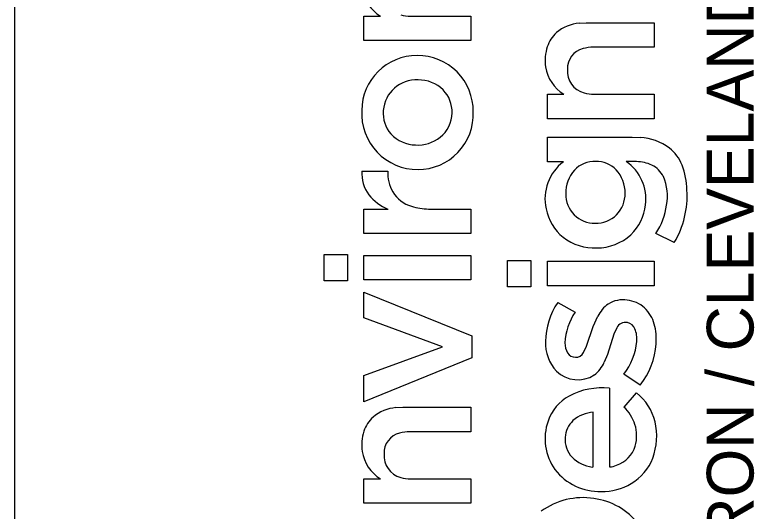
# Model space of a CAD drawing. Extents: x -0.2 to 34, y 0 to 22.
# Drawn here: x 32 to 32.901, y 2.778 to 3.382 of the extents above; entities that cross this region are included whole.
import ezdxf

# ---------------------------------------------------------------- set-up
doc = ezdxf.new("R2010")
doc.units = 0
doc.layers.add('SH_Border', color=7, linetype='Continuous')
doc.layers.add('SH_Named_Boundary', color=7, linetype='Continuous')

msp = doc.modelspace()

# ---------------------------------------------------------------- linework, layer by layer
at = {"layer": 'SH_Border'}
msp.add_line((32, 0.5), (32, 21.5), dxfattribs=at)
at = {"layer": 'SH_Named_Boundary'}
for p, q in [((32.42542, 3.38066), (32.44552, 3.38071)), ((32.42542, 3.35086), (32.42542, 3.38066)), ((32.48222, 3.38071), (32.55569, 3.38071)), ((32.55569, 3.38071), (32.55571, 3.35096)), ((32.68784, 3.3722), (32.69634, 3.37266)), ((32.69634, 3.37266), (32.77916, 3.37266)), ((32.77916, 3.37266), (32.77917, 3.34287)), ((32.55571, 3.35096), (32.42542, 3.35086)), ((32.77917, 3.34287), (32.70485, 3.3428)), ((32.64888, 3.2855), (32.66897, 3.28555)), ((32.64888, 3.25569), (32.64888, 3.2855)), ((32.70568, 3.28555), (32.77915, 3.28555)), ((32.77915, 3.28555), (32.77917, 3.25579)), ((32.77917, 3.25579), (32.64888, 3.25569)), ((32.6489, 3.20336), (32.64889, 3.23322)), ((32.64889, 3.23322), (32.75236, 3.23322)), ((32.75236, 3.23322), (32.76191, 3.23285)), ((32.66836, 3.20336), (32.6489, 3.20336)), ((32.75763, 3.20356), (32.74487, 3.20361)), ((32.42299, 3.19193), (32.45454, 3.19193)), ((32.42542, 3.14577), (32.45473, 3.14579)), ((32.42542, 3.11593), (32.42542, 3.14577)), ((32.50413, 3.14581), (32.55571, 3.14573)), ((32.55571, 3.14573), (32.55565, 3.11593)), ((32.55565, 3.11593), (32.42542, 3.11593)), ((32.8036, 3.10491), (32.7812, 3.11598)), ((32.37705, 3.05818), (32.37705, 3.09026)), ((32.37705, 3.09026), (32.40543, 3.09026)), ((32.40543, 3.09026), (32.40543, 3.05818)), ((32.42542, 3.05942), (32.42542, 3.08928)), ((32.42542, 3.08928), (32.55571, 3.08928)), ((32.55571, 3.08928), (32.55571, 3.05942)), ((32.60051, 3.05111), (32.60051, 3.08319)), ((32.60051, 3.08319), (32.62889, 3.08319)), ((32.62889, 3.08319), (32.62889, 3.05111)), ((32.64888, 3.05234), (32.64888, 3.0822)), ((32.64888, 3.0822), (32.77917, 3.0822)), ((32.77917, 3.0822), (32.77917, 3.05234)), ((32.40543, 3.05818), (32.37705, 3.05818)), ((32.55571, 3.05942), (32.42542, 3.05942)), ((32.62889, 3.05111), (32.60051, 3.05111)), ((32.77917, 3.05234), (32.64888, 3.05234)), ((32.42542, 3.01327), (32.42542, 3.0446)), ((32.42542, 3.0446), (32.5567, 2.9913)), ((32.66151, 3.03207), (32.68268, 3.02025)), ((32.52117, 2.97798), (32.42542, 3.01327)), ((32.70483, 3.00258), (32.71036, 3.01526)), ((32.69675, 2.97868), (32.70483, 3.00258)), ((32.73342, 3.00101), (32.72985, 2.9933)), ((32.5567, 2.9913), (32.5567, 2.96441)), ((32.72985, 2.9933), (32.72213, 2.96882)), ((32.42542, 2.94294), (32.52117, 2.97798)), ((32.69299, 2.97117), (32.69675, 2.97868)), ((32.5567, 2.96441), (32.42542, 2.91086)), ((32.72213, 2.96882), (32.71822, 2.95921)), ((32.42542, 2.91086), (32.42542, 2.94294)), ((32.76214, 2.93141), (32.74198, 2.94469)), ((32.72453, 2.92747), (32.72463, 2.83195)), ((32.74228, 2.90465), (32.75768, 2.922)), ((32.46439, 2.90397), (32.47289, 2.90443)), ((32.47289, 2.90443), (32.55571, 2.90443)), ((32.55571, 2.90443), (32.55571, 2.87465)), ((32.70489, 2.83182), (32.70489, 2.89834)), ((32.55571, 2.87465), (32.4814, 2.87457)), ((32.70361, 2.83165), (32.70489, 2.83182)), ((32.42542, 2.81728), (32.44552, 2.81733)), ((32.42542, 2.78747), (32.42542, 2.81728)), ((32.48222, 2.81733), (32.55569, 2.81733)), ((32.55569, 2.81733), (32.55571, 2.78756)), ((32.55571, 2.78756), (32.42542, 2.78747))]:
    msp.add_line(p, q, dxfattribs=at)
for points in [[(32.42542, 3.35086), (32.42542, 3.38066), (32.44552, 3.38071)], [(32.48222, 3.38071), (32.55569, 3.38071), (32.55571, 3.35096), (32.42542, 3.35086)], [(32.68784, 3.3722), (32.69634, 3.37266), (32.77916, 3.37266), (32.77917, 3.34287), (32.70485, 3.3428)], [(32.64888, 3.25569), (32.64888, 3.2855), (32.66897, 3.28555)], [(32.70568, 3.28555), (32.77915, 3.28555), (32.77917, 3.25579), (32.64888, 3.25569)], [(32.66836, 3.20336), (32.6489, 3.20336), (32.64889, 3.23322), (32.75236, 3.23322), (32.76191, 3.23285)], [(32.75763, 3.20356), (32.74487, 3.20361)], [(32.42299, 3.19193), (32.45454, 3.19193)], [(32.50413, 3.14581), (32.55571, 3.14573), (32.55565, 3.11593), (32.42542, 3.11593)], [(32.42542, 3.11593), (32.42542, 3.14577), (32.45473, 3.14579)], [(32.8036, 3.10491), (32.7812, 3.11598)], [(32.66151, 3.03207), (32.68268, 3.02025)], [(32.69299, 2.97117), (32.69675, 2.97868), (32.70483, 3.00258), (32.71036, 3.01526)], [(32.73342, 3.00101), (32.72985, 2.9933), (32.72213, 2.96882), (32.71822, 2.95921)], [(32.76214, 2.93141), (32.74198, 2.94469)], [(32.72453, 2.92747), (32.72463, 2.83195)], [(32.74228, 2.90465), (32.75768, 2.922)], [(32.46439, 2.90397), (32.47289, 2.90443), (32.55571, 2.90443), (32.55571, 2.87465), (32.4814, 2.87457)], [(32.70361, 2.83165), (32.70489, 2.83182), (32.70489, 2.89834)], [(32.42542, 2.78747), (32.42542, 2.81728), (32.44552, 2.81733)], [(32.48222, 2.81733), (32.55569, 2.81733), (32.55571, 2.78756), (32.42542, 2.78747)]]:
    msp.add_lwpolyline(points, dxfattribs=at)
for points in [[(32.37705, 3.05818), (32.37705, 3.09026), (32.40543, 3.09026), (32.40543, 3.05818)], [(32.42542, 3.05942), (32.42542, 3.08928), (32.55571, 3.08928), (32.55571, 3.05942)], [(32.60051, 3.05111), (32.60051, 3.08319), (32.62889, 3.08319), (32.62889, 3.05111)], [(32.64888, 3.05234), (32.64888, 3.0822), (32.77917, 3.0822), (32.77917, 3.05234)], [(32.42542, 2.91086), (32.42542, 2.94294), (32.52117, 2.97798), (32.42542, 3.01327), (32.42542, 3.0446), (32.5567, 2.9913), (32.5567, 2.96441)]]:
    msp.add_lwpolyline(points, close=True, dxfattribs=at)
for centre, radius, start, end in [((32.47027, 3.42141), 0.04763, 188.96462, 238.69865), ((32.47027, 3.42141), 0.04763, 188.96462, 238.69865), ((32.48183, 3.42286), 0.04215, 254.08913, 270.52838), ((32.48183, 3.42286), 0.04215, 254.08913, 270.52838), ((32.69216, 3.32251), 0.04988, 94.97056, 130.22484), ((32.69216, 3.32251), 0.04988, 94.97056, 130.22484), ((32.68694, 3.33085), 0.04016, 132.22383, 161.68229), ((32.68694, 3.33085), 0.04016, 132.22383, 161.68229), ((32.70217, 3.32642), 0.05602, 162.27398, 187.79173), ((32.70217, 3.32642), 0.05602, 162.27398, 187.79173), ((32.70453, 3.29679), 0.04601, 89.60515, 105.33026), ((32.70453, 3.29679), 0.04601, 89.60515, 105.33026), ((32.69828, 3.31689), 0.02498, 103.68683, 182.21395), ((32.69828, 3.31689), 0.02498, 103.68683, 182.21395), ((32.49014, 3.26543), 0.0674, 89.84756, 179.64047), ((32.49014, 3.26543), 0.0674, 89.84756, 179.64047), ((32.49057, 3.26474), 0.0681, 359.54009, 90.21138), ((32.49057, 3.26474), 0.0681, 359.54009, 90.21138), ((32.69372, 3.32624), 0.04763, 188.96462, 238.69865), ((32.69372, 3.32624), 0.04763, 188.96462, 238.69865), ((32.7008, 3.31381), 0.02757, 175.58441, 255.13816), ((32.7008, 3.31381), 0.02757, 175.58441, 255.13816), ((32.48923, 3.26263), 0.0404, 87.04809, 175.57259), ((32.48923, 3.26263), 0.0404, 87.04809, 175.57259), ((32.49204, 3.25999), 0.04299, 45.84264, 90.98008), ((32.49204, 3.25999), 0.04299, 45.84264, 90.98008), ((32.49458, 3.26421), 0.03821, 357.88569, 44.15902), ((32.49458, 3.26421), 0.03821, 357.88569, 44.15902), ((32.70529, 3.32769), 0.04215, 254.08913, 270.52838), ((32.70529, 3.32769), 0.04215, 254.08913, 270.52838), ((32.49083, 3.26209), 0.06819, 176.8344, 270.40384), ((32.49083, 3.26209), 0.06819, 176.8344, 270.40384), ((32.48729, 3.2625), 0.03848, 175.15378, 221.14706), ((32.48729, 3.2625), 0.03848, 175.15378, 221.14706), ((32.49123, 3.26139), 0.06749, 270.06243, 2.37759), ((32.49123, 3.26139), 0.06749, 270.06243, 2.37759), ((32.49446, 3.26318), 0.0383, 308.28936, 359.43468), ((32.49446, 3.26318), 0.0383, 308.28936, 359.43468), ((32.48919, 3.26607), 0.04228, 223.09994, 268.80895), ((32.48919, 3.26607), 0.04228, 223.09994, 268.80895), ((32.49096, 3.2679), 0.04418, 266.56515, 308.06078), ((32.49096, 3.2679), 0.04418, 266.56515, 308.06078), ((32.75907, 3.16789), 0.06503, 53.40344, 87.49062), ((32.75907, 3.16789), 0.06503, 53.40344, 87.49062), ((32.76517, 3.18039), 0.05141, 21.60748, 50.5577), ((32.76517, 3.18039), 0.05141, 21.60748, 50.5577), ((32.70292, 3.15813), 0.05692, 127.37482, 192.22468), ((32.70292, 3.15813), 0.05692, 127.37482, 192.22468), ((32.70693, 3.16927), 0.0346, 88.47302, 136.42562), ((32.70693, 3.16927), 0.0346, 88.47302, 136.42562), ((32.70814, 3.16963), 0.03424, 44.27195, 90.47623), ((32.70814, 3.16963), 0.03424, 44.27195, 90.47623), ((32.71421, 3.15829), 0.05472, 352.1125, 55.92295), ((32.71421, 3.15829), 0.05472, 352.1125, 55.92295), ((32.75666, 3.15725), 0.04633, 65.01687, 88.8011), ((32.75666, 3.15725), 0.04633, 65.01687, 88.8011), ((32.7626, 3.17155), 0.03085, 26.26808, 63.80301), ((32.7626, 3.17155), 0.03085, 26.26808, 63.80301), ((32.73069, 3.16714), 0.08835, 1.15143, 21.3627), ((32.73069, 3.16714), 0.08835, 1.15143, 21.3627), ((32.46616, 3.18882), 0.04329, 175.87313, 216.34747), ((32.46616, 3.18882), 0.04329, 175.87313, 216.34747), ((32.50087, 3.18948), 0.04639, 176.9688, 209.60636), ((32.50087, 3.18948), 0.04639, 176.9688, 209.60636), ((32.71141, 3.16602), 0.0401, 137.46739, 182.33237), ((32.71141, 3.16602), 0.0401, 137.46739, 182.33237), ((32.70368, 3.166), 0.03996, 358.57141, 43.53765), ((32.70368, 3.166), 0.03996, 358.57141, 43.53765), ((32.73565, 3.16154), 0.05953, 349.30734, 23.43071), ((32.73565, 3.16154), 0.05953, 349.30734, 23.43071), ((32.47466, 3.19716), 0.05511, 218.09809, 248.7907), ((32.47466, 3.19716), 0.05511, 218.09809, 248.7907), ((32.49514, 3.18814), 0.04079, 211.94466, 253.2028), ((32.49514, 3.18814), 0.04079, 211.94466, 253.2028), ((32.70645, 3.1637), 0.03511, 178.88208, 271.08374), ((32.70645, 3.1637), 0.03511, 178.88208, 271.08374), ((32.70818, 3.16404), 0.03546, 268.27882, 1.55016), ((32.70818, 3.16404), 0.03546, 268.27882, 1.55016), ((32.70538, 3.16244), 0.11383, 329.6388, 3.25998), ((32.70538, 3.16244), 0.11383, 329.6388, 3.25998), ((32.50465, 3.2165), 0.07069, 252.46555, 269.57296), ((32.50465, 3.2165), 0.07069, 252.46555, 269.57296), ((32.70463, 3.15696), 0.05837, 190.75182, 231.28919), ((32.70463, 3.15696), 0.05837, 190.75182, 231.28919), ((32.70988, 3.15708), 0.05887, 313.74196, 353.8554), ((32.70988, 3.15708), 0.05887, 313.74196, 353.8554), ((32.70738, 3.16334), 0.08771, 327.31495, 351.57478), ((32.70738, 3.16334), 0.08771, 327.31495, 351.57478), ((32.70632, 3.16112), 0.06269, 232.46061, 272.59022), ((32.70632, 3.16112), 0.06269, 232.46061, 272.59022), ((32.70954, 3.15901), 0.06051, 269.6361, 312.70877), ((32.70954, 3.15901), 0.06051, 269.6361, 312.70877), ((32.73636, 2.98258), 0.08973, 146.53104, 178.7571), ((32.73636, 2.98258), 0.08973, 146.53104, 178.7571), ((32.74661, 2.99713), 0.04053, 125.51182, 153.41595), ((32.74661, 2.99713), 0.04053, 125.51182, 153.41595), ((32.7406, 3.0026), 0.03263, 80.17192, 122.51969), ((32.7406, 3.0026), 0.03263, 80.17192, 122.51969), ((32.74278, 2.99824), 0.03667, 47.79344, 84.68918), ((32.74278, 2.99824), 0.03667, 47.79344, 84.68918), ((32.74519, 2.9789), 0.07495, 146.51121, 176.91007), ((32.74519, 2.9789), 0.07495, 146.51121, 176.91007), ((32.73788, 2.9946), 0.04267, 14.9966, 46.20632), ((32.73788, 2.9946), 0.04267, 14.9966, 46.20632), ((32.74384, 2.99631), 0.01143, 76.66094, 155.7053), ((32.74384, 2.99631), 0.01143, 76.66094, 155.7053), ((32.74397, 2.99511), 0.01256, 21.5098, 78.52618), ((32.74397, 2.99511), 0.01256, 21.5098, 78.52618), ((32.71044, 2.98674), 0.07121, 355.83062, 15.39138), ((32.71044, 2.98674), 0.07121, 355.83062, 15.39138), ((32.72592, 2.98766), 0.03209, 354.57264, 22.06805), ((32.72592, 2.98766), 0.03209, 354.57264, 22.06805), ((32.69666, 2.98238), 0.05005, 177.53659, 222.79318), ((32.69666, 2.98238), 0.05005, 177.53659, 222.79318), ((32.6931, 2.98233), 0.02276, 178.47474, 211.08679), ((32.6931, 2.98233), 0.02276, 178.47474, 211.08679), ((32.68248, 2.99149), 0.0757, 321.81101, 354.79685), ((32.68248, 2.99149), 0.0757, 321.81101, 354.79685), ((32.68952, 2.9882), 0.09219, 321.9777, 355.87384), ((32.68952, 2.9882), 0.09219, 321.9777, 355.87384), ((32.68331, 2.9767), 0.01148, 212.23676, 268.37769), ((32.68331, 2.9767), 0.01148, 212.23676, 268.37769), ((32.68342, 2.97589), 0.01067, 267.71603, 333.73375), ((32.68342, 2.97589), 0.01067, 267.71603, 333.73375), ((32.68098, 2.9758), 0.04077, 308.08772, 335.98736), ((32.68098, 2.9758), 0.04077, 308.08772, 335.98736), ((32.68599, 2.97535), 0.0375, 225.98539, 302.47965), ((32.68599, 2.97535), 0.0375, 225.98539, 302.47965), ((32.7152, 2.84414), 0.08384, 83.61499, 118.28755), ((32.7152, 2.84414), 0.08384, 83.61499, 118.28755), ((32.71744, 2.87167), 0.06443, 13.53365, 51.36148), ((32.71744, 2.87167), 0.06443, 13.53365, 51.36148), ((32.70239, 2.86906), 0.05583, 118.83082, 160.62438), ((32.70239, 2.86906), 0.05583, 118.83082, 160.62438), ((32.46871, 2.85428), 0.04988, 94.96958, 130.22249), ((32.46871, 2.85428), 0.04988, 94.96958, 130.22249), ((32.70378, 2.86556), 0.05486, 19.03571, 45.44059), ((32.70378, 2.86556), 0.05486, 19.03571, 45.44059), ((32.46348, 2.86263), 0.04015, 132.22192, 161.68183), ((32.46348, 2.86263), 0.04015, 132.22192, 161.68183), ((32.70785, 2.85609), 0.04235, 94.00805, 130.88169), ((32.70785, 2.85609), 0.04235, 94.00805, 130.88169), ((32.71041, 2.86612), 0.06437, 160.52012, 215.78311), ((32.71041, 2.86612), 0.06437, 160.52012, 215.78311), ((32.70048, 2.86628), 0.02985, 132.98507, 177.179), ((32.70048, 2.86628), 0.02985, 132.98507, 177.179), ((32.71069, 2.8697), 0.047, 344.60586, 17.007), ((32.71069, 2.8697), 0.047, 344.60586, 17.007), ((32.70635, 2.86921), 0.07579, 339.3542, 13.37853), ((32.70635, 2.86921), 0.07579, 339.3542, 13.37853), ((32.47872, 2.85819), 0.05601, 162.27355, 187.79185), ((32.47872, 2.85819), 0.05601, 162.27355, 187.79185), ((32.48108, 2.82856), 0.04601, 89.60494, 105.3284), ((32.48108, 2.82856), 0.04601, 89.60494, 105.3284), ((32.47482, 2.84867), 0.02498, 103.68646, 182.21874), ((32.47482, 2.84867), 0.02498, 103.68646, 182.21874), ((32.7017, 2.86503), 0.03115, 175.00126, 223.28301), ((32.7017, 2.86503), 0.03115, 175.00126, 223.28301), ((32.7224, 2.86715), 0.03504, 288.00773, 343.55078), ((32.7224, 2.86715), 0.03504, 288.00773, 343.55078), ((32.47026, 2.85802), 0.04762, 188.96199, 238.70369), ((32.47026, 2.85802), 0.04762, 188.96199, 238.70369), ((32.47735, 2.84558), 0.02756, 175.58538, 255.14386), ((32.47735, 2.84558), 0.02756, 175.58538, 255.14386), ((32.70891, 2.87363), 0.04231, 225.06188, 262.79738), ((32.70891, 2.87363), 0.04231, 225.06188, 262.79738), ((32.71894, 2.8652), 0.0626, 300.94269, 338.73225), ((32.71894, 2.8652), 0.0626, 300.94269, 338.73225), ((32.72474, 2.85216), 0.02021, 269.7003, 294.8711), ((32.72474, 2.85216), 0.02021, 269.7003, 294.8711), ((32.71253, 2.87054), 0.06872, 217.74516, 271.65431), ((32.71253, 2.87054), 0.06872, 217.74516, 271.65431), ((32.48183, 2.85948), 0.04215, 254.09162, 270.52835), ((32.48183, 2.85948), 0.04215, 254.09162, 270.52835), ((32.71549, 2.87241), 0.07056, 269.20477, 300.33412), ((32.71549, 2.87241), 0.07056, 269.20477, 300.33412), ((32.69229, 2.70792), 0.08641, 81.19402, 125.99844), ((32.69229, 2.70792), 0.08641, 81.19402, 125.99844), ((32.69458, 2.71132), 0.08272, 37.85208, 82.40204), ((32.69458, 2.71132), 0.08272, 37.85208, 82.40204)]:
    msp.add_arc(centre, radius, start, end, dxfattribs=at)

# ---------------------------------------------------------------- texts
msp.add_text('AKRON / CLEVELAND / COLUMBUS', height=0.056969, rotation=90, dxfattribs=at).set_placement((32.90012, 2.638))

doc.saveas('drawing.dxf')
